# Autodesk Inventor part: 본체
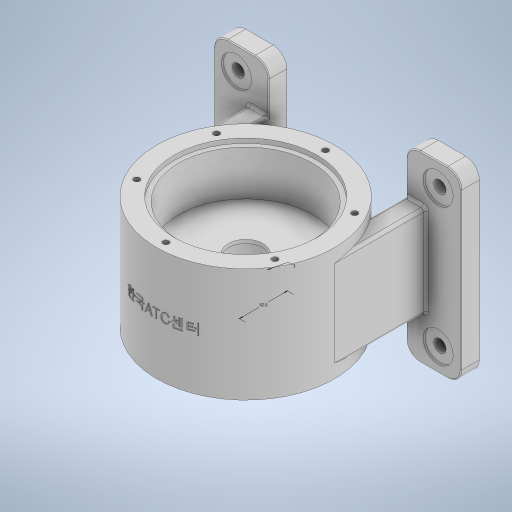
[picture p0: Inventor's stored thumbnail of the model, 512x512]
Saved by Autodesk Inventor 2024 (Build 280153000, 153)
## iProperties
Created: 2025-12
Part Number: 본체
Material: 일반
Document SubType Name: Modeling
Designer: Edu07
Density: 1 g/cm^3
Appearance: 기본값
Author: Edu07
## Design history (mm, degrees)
sketch "스케치3"
  geometry: L1 (135, 85)-(135, -85); L2 (-135, -85)-(-135, 85); L3 (-75, -85)-(-75, 85); L4 (75, 85)-(75, -85); L5 (-120, 100)-(-90, 100); L6 (90, 100)-(120, 100); L7 (120, -100)-(90, -100); L8 (-90, -100)-(-120, -100); C1 r 6.75 at (-110, 75); C2 r 6.75 at (110, 75); C3 r 6.75 at (110, -75); C4 r 6.75 at (-110, -75); A1 r 15 centre (-120, 85) between (-120, 100) and (-135, 85); A2 r 15 centre (-90, 85) between (-75, 85) and (-90, 100); A3 r 15 centre (-90, -85) between (-90, -100) and (-75, -85); A4 r 15 centre (-120, -85) between (-135, -85) and (-120, -100); A5 r 15 centre (90, 85) between (90, 100) and (75, 85); A6 r 15 centre (120, 85) between (135, 85) and (120, 100); A7 r 15 centre (120, -85) between (120, -100) and (135, -85); A8 r 15 centre (90, -85) between (75, -85) and (90, -100); 3 further points
  constraints: 16 end point, 16 point on circle, 16 tangent, 12 centre point, 7 equal radius, 7 parallel, 4 point on line, 2 perpendicular
  dimensions: "d4" = 200 distance of point (135, 100) point (135, -100); "d5" = 60 distance between parallel lines of L2 L3; "d6" = 60 distance between parallel lines of L1 L4; "d7" = 15 radius of A1; "d10" = 13.5 diameter of C1; "d11" = 13.5 diameter of C2; "d12" = 13.5 diameter of C3; "d13" = 13.5 diameter of C4
extrude "돌출3" new body sketch "스케치3" distance "d16" = 20; taper "d17" = 0 deg
sketch "스케치4"
  geometry: C1 r 6.75 at (-110, 75) reference; C2 r 16.5 at (-110, 75); C3 r 6.75 at (-110, -75) reference; C4 r 16.5 at (-110, -75); C5 r 6.75 at (110, 75) reference; C6 r 16.5 at (110, 75); C7 r 6.75 at (110, -75) reference; C8 r 16.5 at (110, -75); 1 further point
  constraints: 4 centre point, 4 coincident
  dimensions: "d18" = 33 diameter of C2; "d19" = 33 diameter of C4; "d20" = 33 diameter of C6; "d21" = 33 diameter of C8
extrude "돌출4" cut sketch "스케치4" distance "d22" = 2; taper "d23" = 0 deg
sketch "스케치6"
  geometry: L1 (0, 0)-(0, 120); C1 r 97 at (0, 120)
  constraints: 2 end point, 1 centre point, 1 coincident, 1 vertical
  dimensions: "d24" = 120 distance of L1.start L1.end; "d25" = 194 diameter of C1
extrude "돌출5" join sketch "스케치6" stored distance "d26" = 124; taper "d27" = 0 deg
node "작업 평면2"
sketch "스케치7"
  geometry: 2 further points
  constraints: 2 coincident, 1 other
feature "엠보싱1" sketch "스케치7" dims "d5" = 60, "d29" = 0.5, "d30" = 0
sketch "스케치9"
  geometry: L1 (75, 20)-(75, 58.486) reference; L2 (75, 0)-(75, 20) reference; L3 (75, 20)-(97, 20); L4 (120, 20)-(90, 20) reference; L5 (97, 20)-(97, 120); L6 (75, 20)-(75, 58.486); A1 r 97 centre (0, 120) between (75, 58.486) and (97, 120) reference; A2 r 97 centre (0, 120) between (75, 58.486) and (97, 120); 1 further point
  constraints: 6 end point, 3 point on circle, 1 centre point, 1 collinear, 1 concentric, 1 perpendicular, 1 point on line
  dimensions: "d38" = 22 distance of L1.start L3.end
extrude "돌출6" join sketch "스케치9" stored distance "d39" = 100; taper "d40" = 0 deg
sketch "스케치10"
  geometry: C1 r 78 at (0, 0); 1 further point
  constraints: 1 centre point
  dimensions: "d43" = 156 diameter of C1
extrude "돌출7" cut sketch "스케치10" distance "d44" = 5; taper "d45" = 0 deg
sketch "스케치11"
  geometry: C1 r 78 at (0, 0) reference; C2 r 73 at (0, 0); 1 further point
  constraints: 1 centre point, 1 coincident
  dimensions: "d46" = 146 diameter of C2
  node "투영된 루프2"
sketch "스케치12"
  geometry: 1 further point
extrude "돌출8" cut sketch "스케치11" distance "d47" = 17; taper "d48" = 0 deg
sketch "스케치13"
  geometry: C1 r 73 at (0, 0) reference; C2 r 87 at (0, 0); 1 further point
  constraints: 1 centre point, 1 coincident
  dimensions: "d49" = 174 diameter of C2
extrude "돌출9" cut sketch "스케치13" distance "d50" = 32; taper "d51" = 0 deg
sketch "스케치14"
  geometry: C1 r 73 at (0, 0) reference; C2 r 21 at (0, 0); 1 further point
  constraints: 1 centre point, 1 coincident
  dimensions: "d52" = 42 diameter of C2
extrude "돌출10" cut sketch "스케치14" distance "d53" = 12; taper "d54" = 0 deg
sketch "스케치15"
  geometry: C1 r 19 at (0, 0); 1 further point
  constraints: 1 centre point
  dimensions: "d55" = 38 diameter of C1
extrude "돌출11" cut sketch "스케치15" distance "d56" = 12; taper "d57" = 0 deg
sketch "스케치16" dims "d58" = 174
  geometry: 3 further points
  constraints: 1 vertical alignment, 2 other
hole "구멍1" sketch "스케치16" at (0, 87) diameter "d59" = 6.647; stored, may be unused: countersink angle "d63" = 82 deg, drill point angle "d65" = 118 deg; dims "d60" = 16, "d61" = 3.023, "d62" = 2, "d64" = 18
sketch "스케치18"
  geometry: L1 (0, 0)-(0, -52.5); L2 (0, -52.5)-(38.184, -52.5); L3 (-23.156, -38.614)-(-35.967, -59.978); C1 r 21 at (0, -52.5); A1 r 27 centre (0, -52.5) between (-23.156, -38.614) and (-20.51, -70.06) reference; A2 r 73 centre (0, 0) between (-20.51, -70.06) and (20.51, -70.06); A3 r 3 centre (-38.54, -58.435) between (-40.191, -60.94) and (-35.967, -59.978); 3 further points
  constraints: 8 point on circle, 6 end point, 4 centre point, 3 coincident, 3 tangent, 1 horizontal, 1 point on line, 1 vertical, 4 other
  dimensions: "d71" = 52.5 distance of L1.start L1.end; "d75" = 3 radius of A3 (derived)
sketch "스케치19"
  geometry: L1 (75, 8)-(36.6, 30.17); L2 (75, 58.486)-(75, 20) reference; L3 (75, 8)-(75, 58.486); C1 r 3.324 at (75.344, 163.5) reference; C2 r 3.324 at (75.344, 76.5) reference; C3 r 3.324 at (0, 33) reference; C4 r 3.324 at (-75.344, 76.5) reference; C5 r 3.324 at (-75.344, 163.5) reference; C6 r 3.324 at (0, 207) reference; C7 r 78 at (0, 120) reference; A1 r 97 centre (0, 120) between (75, 58.486) and (36.6, 30.17) reference; 2 further points
  constraints: 4 end point, 2 point on circle
feature "리브2" sketch "스케치19" dims "d78" = 1, "d79" = 12, "d80" = 0, "d81" = 0, "d82" = 1, "d83" = 1
chamfer "모따기1" distance "d84" = 1; stored, may be unused: second distance "d85" = 2, angle "d86" = 30 deg
fillet "모깎기1" dims "d87" = 3
fillet "모깎기2" dims "d88" = 3
fillet "모깎기3" dims "d89" = 3
fillet "모깎기4" dims "d90" = 3
node "솔리드3"
mirror "미러1"
mirror "미러2"
pattern_circular "원형 패턴1" dims angle "d67" = 360 deg
mirror "미러3"
mirror "미러4"
node "투영된 루프3"
node "투영된 루프4"
other parameters: "d28" = 263.25
